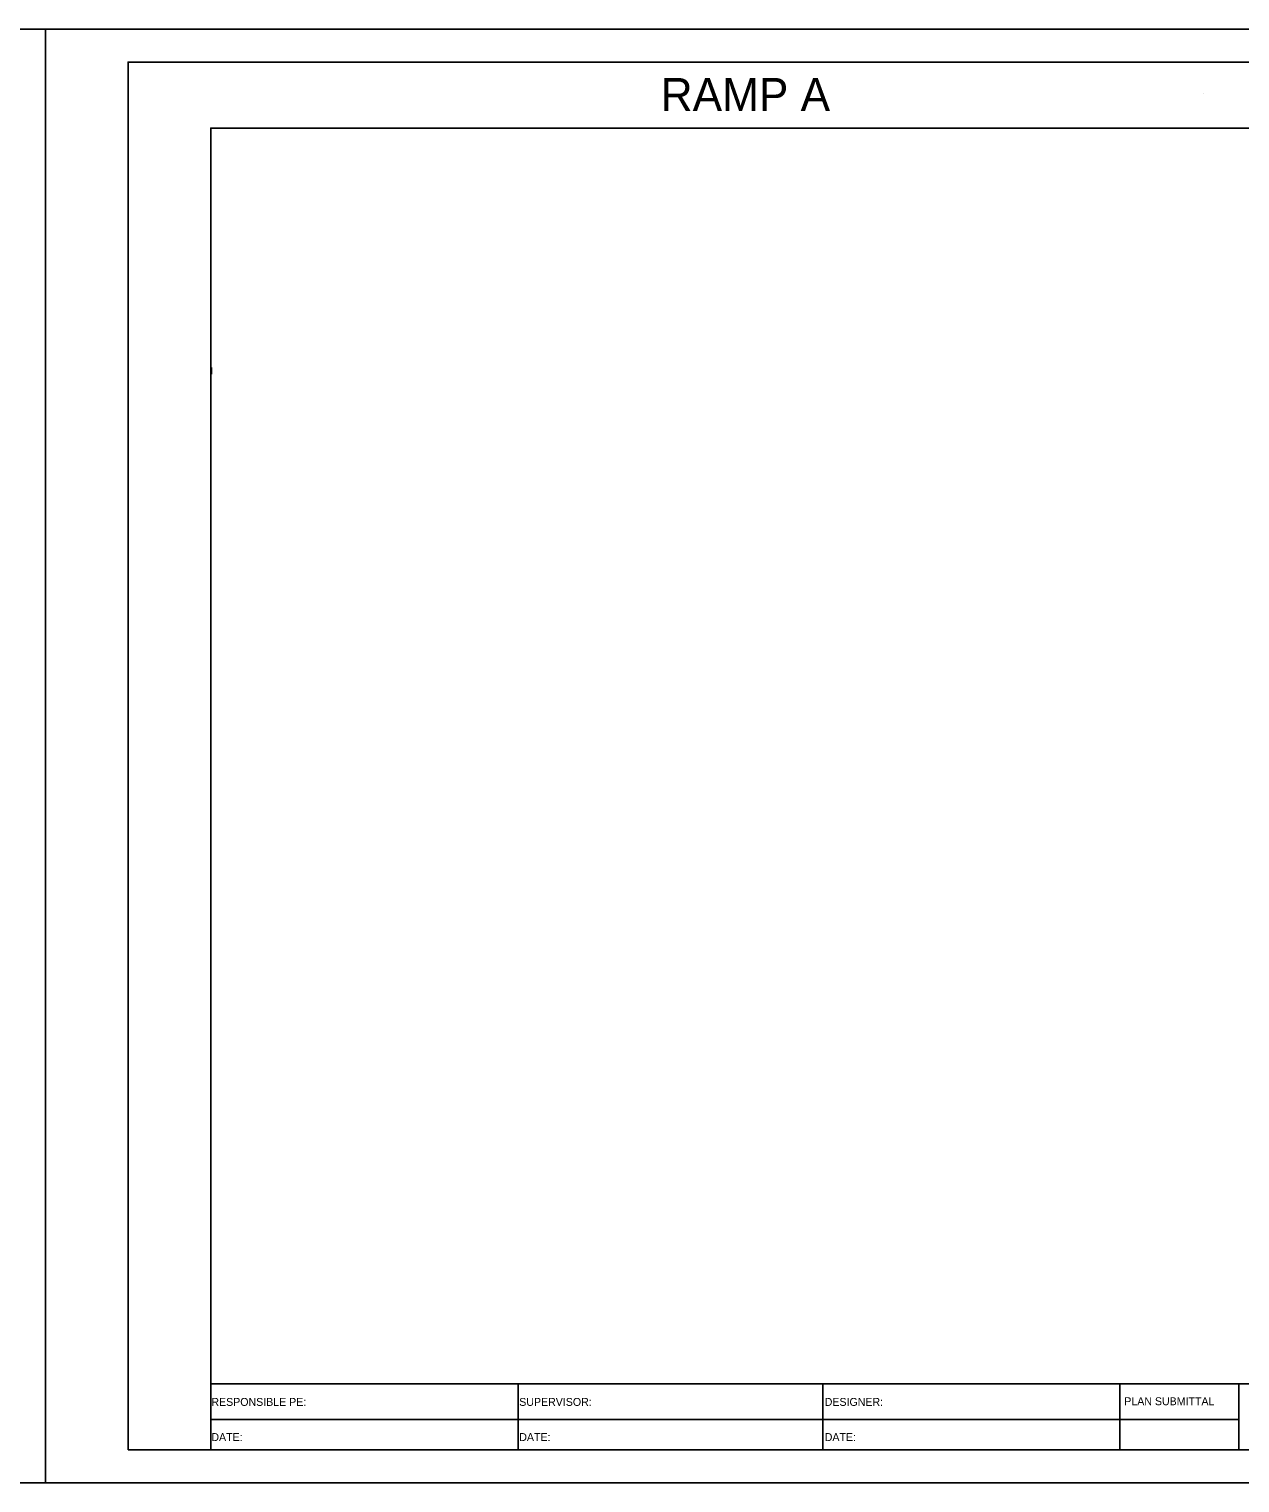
# Model space of a CAD drawing. Extents: x 1797478 to 1804836, y 246529 to 250952.
# Drawn here: x 1802453.5 to 1802636.8, y 250064.4 to 250284.4 of the extents above; entities that cross this region are included whole.
import ezdxf

# ---------------------------------------------------------------- set-up
doc = ezdxf.new("R2010")
doc.units = 0
for name, color, linetype in [('2', 7, 'Continuous'), ('ANNO-SHT', 7, 'Continuous'), ('ANNO-TXT', 7, 'Continuous'), ('AXIS', 7, 'Continuous'), ('DRAINAGE', 7, 'Continuous'), ('Level 1', 7, 'Continuous'), ('Level 62', 7, 'Continuous'), ('SHT-BDR', 7, 'Continuous'), ('SHT-BNDRY', 7, 'Continuous')]:
    doc.layers.add(name, color=color, linetype=linetype)

# ---------------------------------------------------------------- blocks, each defined once
blk = doc.blocks.new('SC47208')
at = {"layer": 'Level 1'}
blk.add_line((0, 0), (0, 0), dxfattribs=at)

msp = doc.modelspace()

# ---------------------------------------------------------------- linework, layer by layer
at = {"layer": '2'}
msp.add_lwpolyline([(1802481.12, 250233.21), (1802481.1, 250232.21)], dxfattribs=at)
msp.add_lwpolyline([(1802481.12, 250233.21), (1802481.1, 250232.21)], dxfattribs=at)
at = {"layer": 'AXIS'}
msp.add_line((1802481, 250189.42), (1802481, 250189.43), dxfattribs=at)
at = {"layer": 'Level 62'}
for points in [[(1802116, 250064.42), (1802456, 250064.42), (1802456, 250284.42), (1802116, 250284.42)], [(1802456, 250064.42), (1802796, 250064.42), (1802796, 250284.42), (1802456, 250284.42)]]:
    msp.add_lwpolyline(points, close=True, dxfattribs=at)
at = {"layer": 'SHT-BDR'}
msp.add_lwpolyline([(1802481, 250079.43), (1802781, 250079.43), (1802781, 250269.43), (1802481, 250269.43)], close=True, dxfattribs=at)
at = {"layer": 'SHT-BNDRY'}
for p, q in [((1802481, 250069.42), (1802481, 250079.43)), ((1802527.52, 250079.43), (1802527.52, 250069.42)), ((1802573.67, 250069.42), (1802573.67, 250079.43)), ((1802618.59, 250069.42), (1802618.59, 250079.43)), ((1802636.63, 250069.42), (1802636.63, 250079.43)), ((1802481, 250074.03), (1802636.63, 250074.03))]:
    msp.add_line(p, q, dxfattribs=at)
msp.add_lwpolyline([(1802468.5, 250069.42), (1802791, 250069.42), (1802791, 250279.42), (1802468.5, 250279.42)], close=True, dxfattribs=at)

# ---------------------------------------------------------------- block references
at = {"layer": 'DRAINAGE', "xscale": 0.2, "yscale": 0.20000000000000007, "rotation": -116.41666666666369}
msp.add_blockref('SC47208', (1802631.32, 250274.62), dxfattribs=at)
msp.add_blockref('SC47208', (1802631.32, 250274.62), dxfattribs=at)

# ---------------------------------------------------------------- texts
at = {"layer": 'ANNO-SHT'}
msp.add_text('                 RAMP A                 ', height=4.9995, rotation=360, dxfattribs=at).set_placement((1802517.54, 250272.02))
at = {"layer": 'ANNO-TXT'}
for s, p in [('RESPONSIBLE PE:', (1802481.1, 250076.08)), ('SUPERVISOR:', (1802527.7, 250076.08)), ('DESIGNER:', (1802573.94, 250076.08)), ('PLAN SUBMITTAL', (1802619.28, 250076.18)), ('DATE:', (1802481.1, 250070.76)), ('DATE:', (1802527.7, 250070.76)), ('DATE:', (1802573.94, 250070.76))]:
    msp.add_text(s, height=1.2, rotation=360, dxfattribs=at).set_placement(p)

doc.saveas('drawing.dxf')
